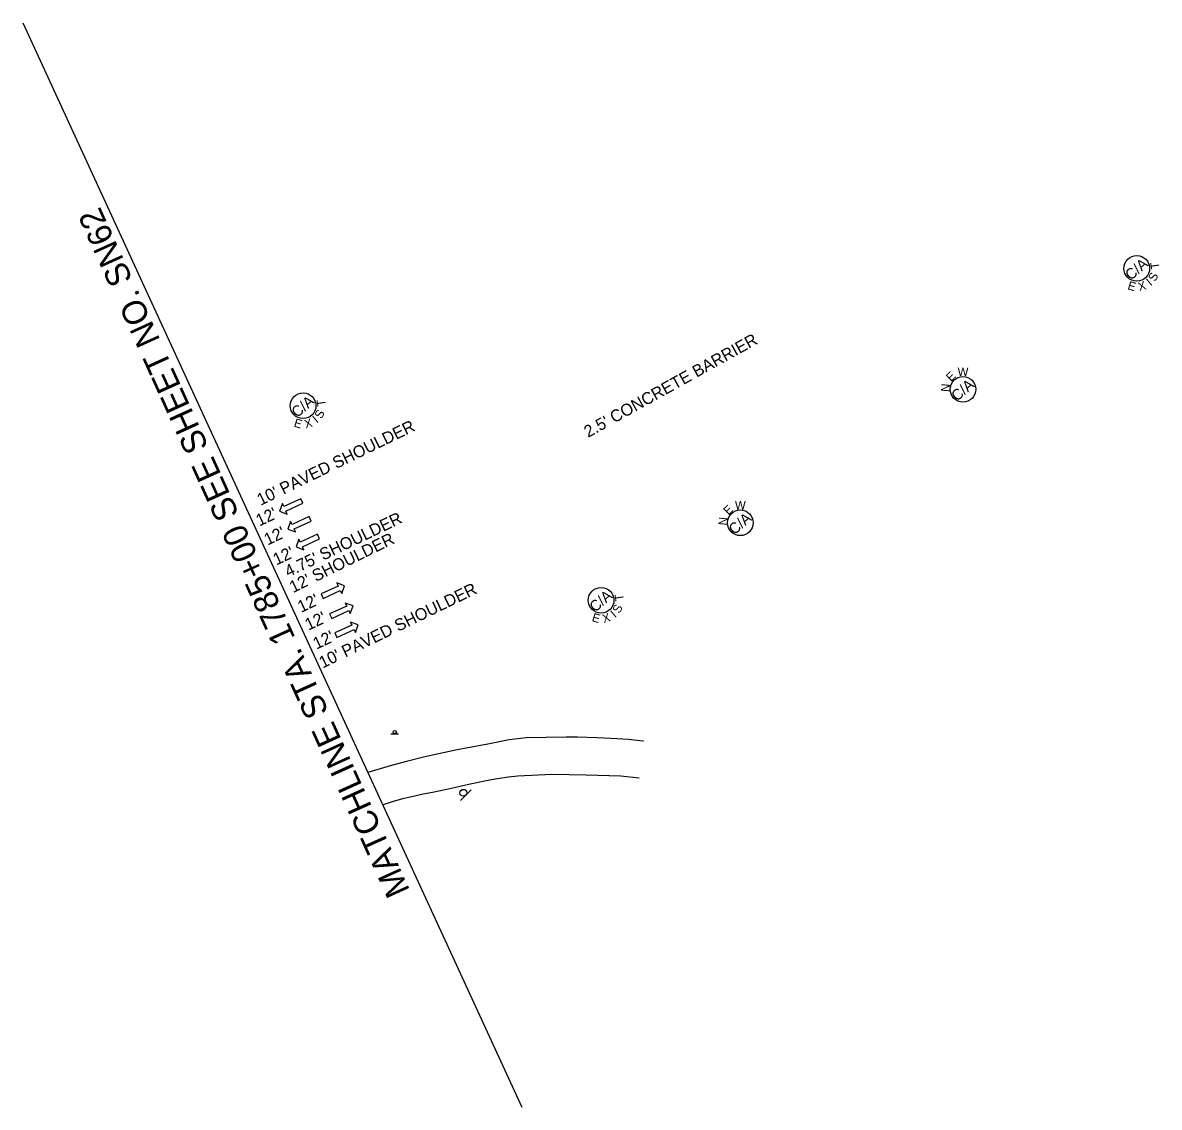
# Model space of a CAD drawing. Extents: x 1824788 to 1826426, y 1192883 to 1194457.
# Drawn here: x 1824788 to 1825453, y 1192883 to 1193517 of the extents above; entities that cross this region are included whole.
import ezdxf

# ---------------------------------------------------------------- set-up
doc = ezdxf.new("R2010")
doc.units = 0
for name, color, linetype in [('RD_EX_Road', 7, 'Continuous'), ('RD_PD_Final_LnLine', 7, 'Continuous'), ('RD_PD_Final_TX', 7, 'Continuous'), ('RD_SHT_MatchLine', 7, 'Continuous'), ('RD_SHT_TX', 7, 'Continuous'), ('RD_Sketch10', 7, 'Continuous'), ('RD_Sketch8', 7, 'Continuous'), ('SN_P_Signs', 7, 'Continuous')]:
    doc.layers.add(name, color=color, linetype=linetype)

# ---------------------------------------------------------------- blocks, each defined once
blk = doc.blocks.new('SARRW2')
at = {"layer": 'RD_PD_Final_LnLine'}
blk.add_lwpolyline([(-12, 1.2), (-12, -1.2), (-2.83, -1.2), (-2.83, -2.83), (0, 0), (-2.83, 2.83), (-2.83, 1.2)], close=True, dxfattribs=at)

msp = doc.modelspace()

# ---------------------------------------------------------------- linework, layer by layer
at = {"layer": 'RD_EX_Road'}
for points in [[(1825151.1, 1193096.67), (1825150.67, 1193096.73), (1825142.29, 1193097.62), (1825135.57, 1193098.06), (1825124, 1193098.67), (1825112.42, 1193099.07), (1825105.86, 1193099.09), (1825094.1, 1193098.95), (1825082.36, 1193098.62), (1825072.55, 1193097.49), (1825059.98, 1193095.07), (1825047.4, 1193092.66), (1825042, 1193091.62), (1825032.13, 1193089.56), (1825022.31, 1193087.31), (1825012.53, 1193084.87), (1825002.8, 1193082.24), (1824989.79, 1193078.32)], [(1824998.45, 1193059.5), (1824998.47, 1193059.5), (1825004.34, 1193061.41), (1825010.27, 1193063.13), (1825016.25, 1193064.65), (1825022.27, 1193065.99), (1825027.6, 1193067), (1825038.67, 1193069.26), (1825049.69, 1193071.7), (1825052.68, 1193072.4), (1825059.13, 1193073.76), (1825065.63, 1193074.93), (1825072.16, 1193075.9), (1825077.52, 1193076.55), (1825097.42, 1193077.42), (1825117.55, 1193076.96), (1825137.78, 1193076.54), (1825148.51, 1193075.25)]]:
    msp.add_lwpolyline(points, dxfattribs=at)
at = {"layer": 'RD_SHT_MatchLine'}
msp.add_line((1824787.98, 1193516.92), (1825079.84, 1192882.61), dxfattribs=at)
at = {"layer": 'RD_Sketch10'}
for centre in [(1825337.91, 1193302.51), (1825207.7, 1193224.45)]:
    msp.add_circle(centre, 7.5, dxfattribs=at)
at = {"layer": 'RD_Sketch8'}
for centre in [(1825439.57, 1193373.24), (1824951.97, 1193292.92), (1825126.26, 1193179.13)]:
    msp.add_circle(centre, 7.5, dxfattribs=at)
at = {"layer": 'SN_P_Signs'}
for p, q in [((1825003.32, 1193101.05), (1825007.82, 1193101.05)), ((1825043.96, 1193061.94), (1825050.32, 1193068.3))]:
    msp.add_line(p, q, dxfattribs=at)
for centre, radius in [((1825005.58, 1193102.06), 1), ((1825045.72, 1193066.56), 2)]:
    msp.add_circle(centre, radius, dxfattribs=at)

# ---------------------------------------------------------------- block references
at = {"layer": 'RD_PD_Final_LnLine', "xscale": 1.200000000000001}
for p, yscale, rotation in [((1824938.21, 1193231.16), 1.200000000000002, -155.1613749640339), ((1824943.02, 1193220.75), 1.200000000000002, -155.1613749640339), ((1824947.84, 1193210.35), 1.200000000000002, -155.1613749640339), ((1824976.2, 1193187.59), 1.2000000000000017, 24.838625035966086), ((1824981.16, 1193175.85), 1.2000000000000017, 24.838625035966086), ((1824984.25, 1193164.74), 1.2000000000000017, 24.838625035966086)]:
    msp.add_blockref('SARRW2', p, dxfattribs=dict(at, yscale=yscale, rotation=rotation))

# ---------------------------------------------------------------- texts
at = {"layer": 'RD_PD_Final_TX'}
for s, rotation, p in [("2.5' CONCRETE BARRIER", 29.01803, (1825118.68, 1193274.08)), ("10' PAVED SHOULDER", 25.94209, (1824927.12, 1193234.35)), ("12'", 25.17998, (1824926.39, 1193222.24)), ("4.75' SHOULDER", 25.62175, (1824943.28, 1193192.47)), ("12'", 25.17998, (1824931.15, 1193211.09)), ("12' SHOULDER", 26.17389, (1824946.09, 1193183.25)), ("12'", 25.17998, (1824936.38, 1193199.46)), ("10' PAVED SHOULDER", 25.94209, (1824963.36, 1193139.15)), ("12'", 25.17998, (1824950.76, 1193171.72)), ("12'", 25.17998, (1824955.07, 1193161.33)), ("12'", 25.17998, (1824959.74, 1193150.21))]:
    msp.add_text(s, height=7, rotation=rotation, dxfattribs=at).set_placement(p)
at = {"layer": 'RD_SHT_TX'}
msp.add_text('MATCHLINE STA. 1785+00 SEE SHEET NO. SN62', height=14.1726, rotation=114.39758, dxfattribs=at).set_placement((1825014.61, 1193009.42))
at = {"layer": 'RD_Sketch10'}
for s, height, rotation, p in [('E', 5, 44.71651, (1825330.96, 1193306.72)), ('W', 5, 359.68608, (1825334.75, 1193310.27)), ('C/A', 6.25, 40.38346, (1825334.38, 1193295.21)), ('N', 5, 85.25323, (1825329.99, 1193300.82)), ('E', 5, 44.71651, (1825200.75, 1193228.66)), ('W', 5, 359.68608, (1825204.54, 1193232.21)), ('N', 5, 85.25323, (1825199.79, 1193222.76)), ('C/A', 6.25, 40.38346, (1825204.18, 1193217.15))]:
    msp.add_text(s, height=height, rotation=rotation, dxfattribs=at).set_placement(p)
at = {"layer": 'RD_Sketch8'}
for s, height, rotation, p in [('C/A', 6.25, 40.38346, (1825436.05, 1193365.94)), ('T', 5, 98.56861, (1825452.97, 1193373.21)), ('X', 5, 16.02408, (1825441.14, 1193359.9)), ('I', 5, 40.18408, (1825447.65, 1193362.72)), ('S', 5, 62.1759, (1825450.32, 1193365.22)), ('E', 5, 343.59471, (1825433.84, 1193361.11)), ('C/A', 6.25, 40.38346, (1824948.45, 1193285.62)), ('T', 5, 98.56861, (1824965.37, 1193292.89)), ('I', 5, 40.18408, (1824960.05, 1193282.4)), ('S', 5, 62.1759, (1824962.72, 1193284.9)), ('E', 5, 343.59471, (1824946.23, 1193280.8)), ('X', 5, 16.02408, (1824953.54, 1193279.59)), ('C/A', 6.25, 40.38346, (1825122.74, 1193171.83)), ('T', 5, 98.56861, (1825139.66, 1193179.1)), ('I', 5, 40.18408, (1825134.34, 1193168.61)), ('S', 5, 62.1759, (1825137.01, 1193171.11)), ('E', 5, 343.59471, (1825120.53, 1193167.01)), ('X', 5, 16.02408, (1825127.83, 1193165.8))]:
    msp.add_text(s, height=height, rotation=rotation, dxfattribs=at).set_placement(p)

doc.saveas('drawing.dxf')
